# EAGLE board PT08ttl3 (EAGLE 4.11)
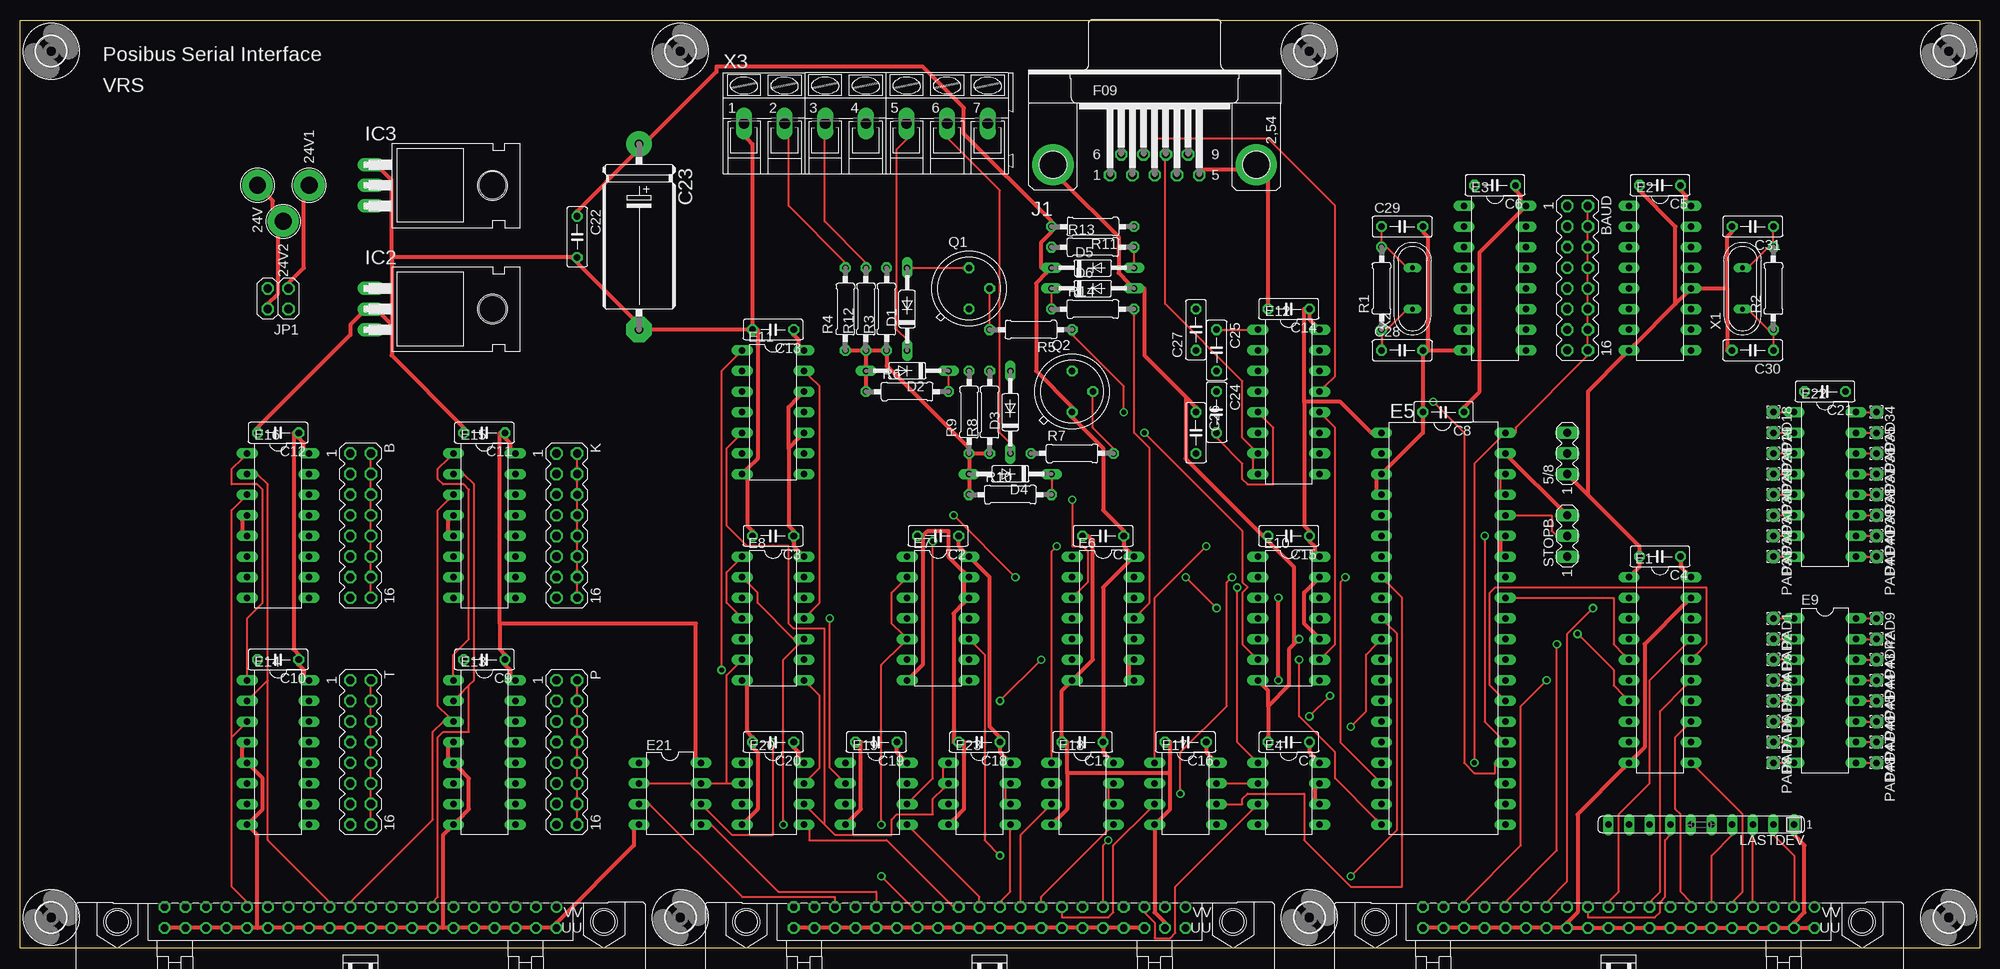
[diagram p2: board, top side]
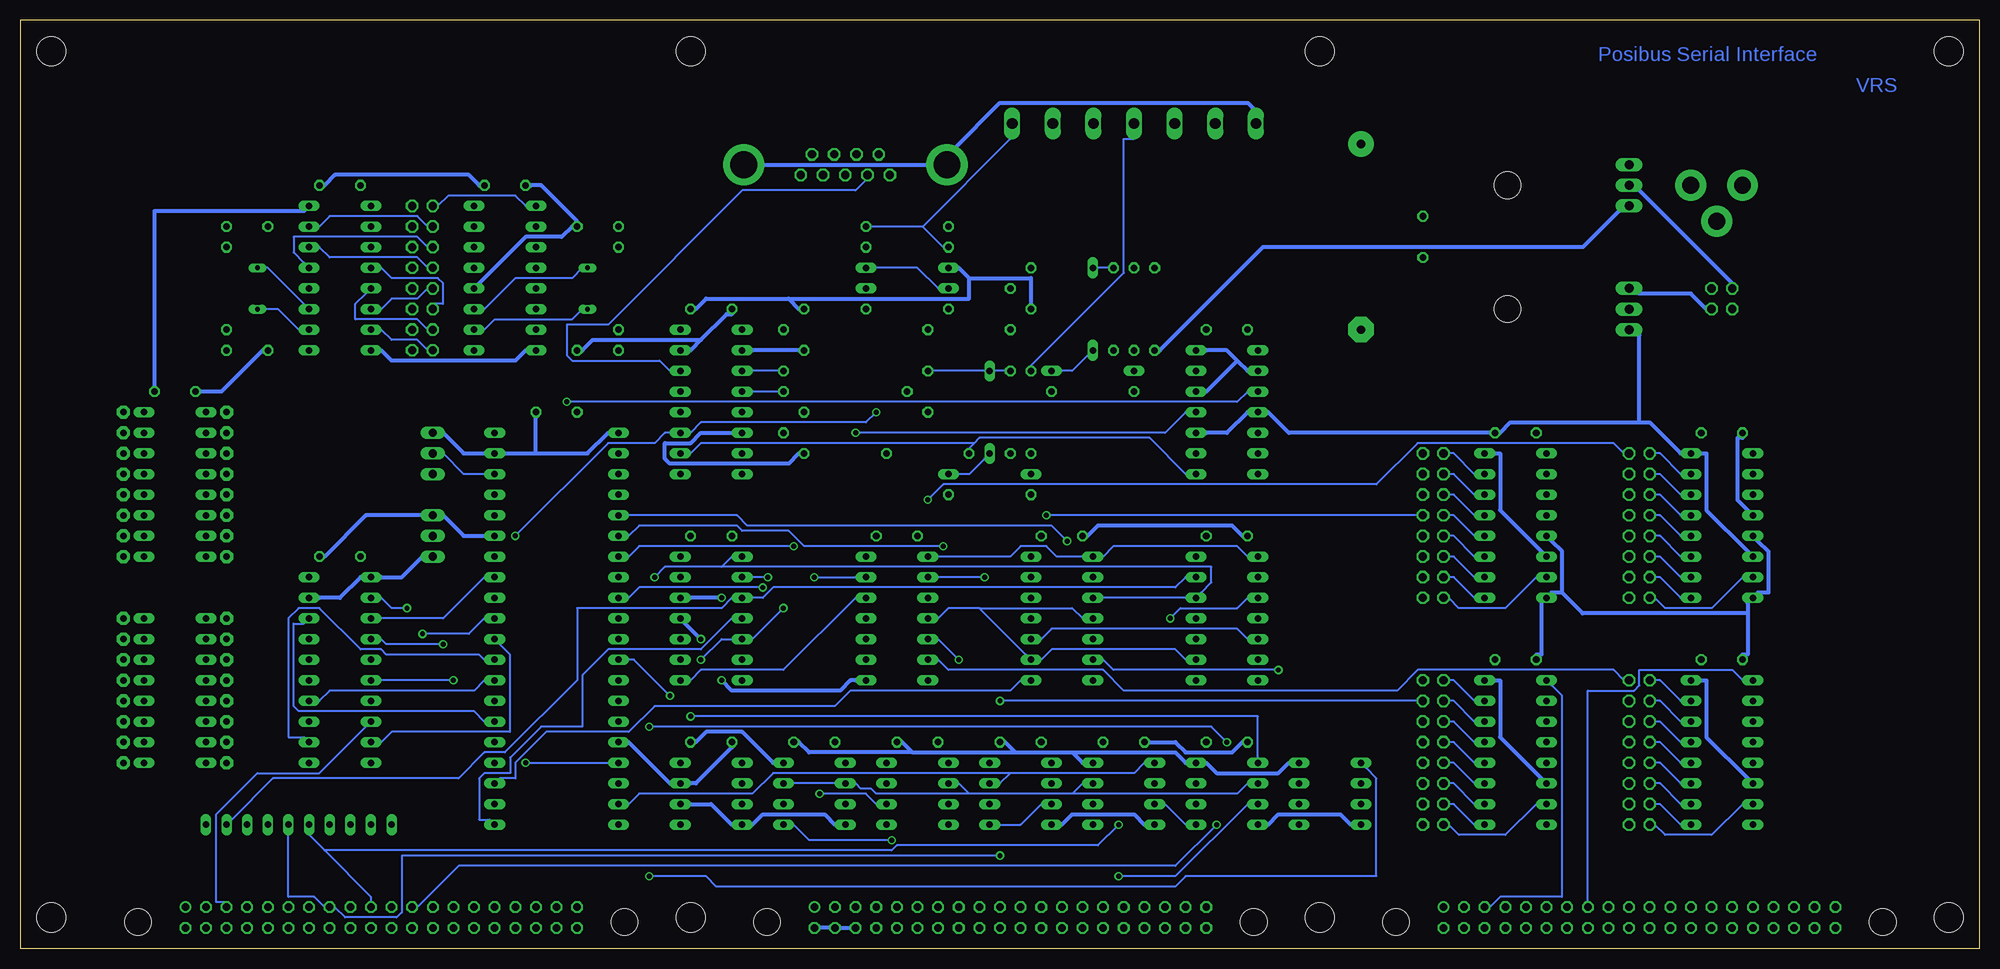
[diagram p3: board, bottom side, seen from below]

Size 241.3 x 114.3 mm. Coordinates in mm from the lower left corner, seen from the top.
Outline: 0,0 0,114.3 241.3,114.3 241.3,0 0,0
Copper layers (1*16): Top 0.035mm / dielectric 1.5mm / Bottom 0.035mm
Design rules "olimex10mil": minimum track width 10mil, minimum drill 24mil, track to track 10mil, track to pad 10mil, pad to pad 10mil, via to via 10mil, smd to smd 10mil, copper to edge 25mil, drill to drill 10mil, minimum pad ring 10mil, minimum via ring 8mil, stop-mask expansion 0mil, vias tented up to drill 0mil, thermal gap 10mil
Net classes: 1 supply: width 0.508 mm

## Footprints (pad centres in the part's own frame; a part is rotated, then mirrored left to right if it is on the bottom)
MA03-1 = drill 1.016 long: 1 -2.54,0; 2 0,0; 3 2.54,0
0820 = drill 2.083 pad 3.81 round: P$1 0,0
MA08-2 = drill 1.016 octagon: 1 -8.89,-1.27; 2 -8.89,1.27; 3 -6.35,-1.27; 4 -6.35,1.27; 5 -3.81,-1.27; 6 -3.81,1.27; 7 -1.27,-1.27; 8 -1.27,1.27; 9 1.27,-1.27; 10 1.27,1.27; 11 3.81,-1.27; 12 3.81,1.27; 13 6.35,-1.27; 14 6.35,1.27; 15 8.89,-1.27; 16 8.89,1.27
C050-025X075 = drill 0.813 octagon: 1 -2.54,0; 2 2.54,0
E22-9 = drill 1.016 pad 3.15 round: + -11.43,0 | drill 1.016 pad 3.15 octagon: - 11.43,0
DO35-10 = drill 0.813 long: A 5.08,0; C -5.08,0
DEC40PINH = drill 0.914 octagon: A 24.13,1.27; AA -3.81,1.27; B 24.13,-1.27; BB -3.81,-1.27; C 21.59,1.27; CC -6.35,1.27; D 21.59,-1.27; DD -6.35,-1.27; E 19.05,1.27; EE -8.89,1.27; F 19.05,-1.27; FF -8.89,-1.27; H 16.51,1.27; HH -11.43,1.27; J 16.51,-1.27; JJ -11.43,-1.27; K 13.97,1.27; KK -13.97,1.27; L 13.97,-1.27; LL -13.97,-1.27; M 11.43,1.27; MM -16.51,1.27; N 11.43,-1.27; NN -16.51,-1.27; P 8.89,1.27; PP -19.05,1.27; R 8.89,-1.27; RR -19.05,-1.27; S 6.35,1.27; SS -21.59,1.27; T 6.35,-1.27; TT -21.59,-1.27; U 3.81,1.27; UU -24.13,1.27; V 3.81,-1.27; W 1.27,1.27; X 1.27,-1.27; Y -1.27,1.27; Z -1.27,-1.27 | drill 0.914 round: VV -24.13,-1.27 | hole 3.302: -29.972,0.533; 29.972,0.533
DIL20 = drill 0.813 long: 1 -11.43,-3.81; 2 -8.89,-3.81; 3 -6.35,-3.81; 4 -3.81,-3.81; 5 -1.27,-3.81; 6 1.27,-3.81; 7 3.81,-3.81; 8 6.35,-3.81; 9 8.89,-3.81; 10 11.43,-3.81; 11 11.43,3.81; 12 8.89,3.81; 13 6.35,3.81; 14 3.81,3.81; 15 1.27,3.81; 16 -1.27,3.81; 17 -3.81,3.81; 18 -6.35,3.81; 19 -8.89,3.81; 20 -11.43,3.81
DIL16 = drill 0.813 long: 1 -8.89,-3.81; 2 -6.35,-3.81; 3 -3.81,-3.81; 4 -1.27,-3.81; 5 1.27,-3.81; 6 3.81,-3.81; 7 6.35,-3.81; 8 8.89,-3.81; 9 8.89,3.81; 10 6.35,3.81; 11 3.81,3.81; 12 1.27,3.81; 13 -1.27,3.81; 14 -3.81,3.81; 15 -6.35,3.81; 16 -8.89,3.81
DIL08 = drill 0.813 long: 1 -3.81,-3.81; 2 -1.27,-3.81; 3 1.27,-3.81; 4 3.81,-3.81; 5 3.81,3.81; 6 1.27,3.81; 7 -1.27,3.81; 8 -3.81,3.81
DIL40 = drill 0.813 long: 1 -24.13,-7.62; 2 -21.59,-7.62; 3 -19.05,-7.62; 4 -16.51,-7.62; 5 -13.97,-7.62; 6 -11.43,-7.62; 7 -8.89,-7.62; 8 -6.35,-7.62; 9 -3.81,-7.62; 10 -1.27,-7.62; 11 1.27,-7.62; 12 3.81,-7.62; 13 6.35,-7.62; 14 8.89,-7.62; 15 11.43,-7.62; 16 13.97,-7.62; 17 16.51,-7.62; 18 19.05,-7.62; 19 21.59,-7.62; 20 24.13,-7.62; 21 24.13,7.62; 22 21.59,7.62; 23 19.05,7.62; 24 16.51,7.62; 25 13.97,7.62; 26 11.43,7.62; 27 8.89,7.62; 28 6.35,7.62; 29 3.81,7.62; 30 1.27,7.62; 31 -1.27,7.62; 32 -3.81,7.62; 33 -6.35,7.62; 34 -8.89,7.62; 35 -11.43,7.62; 36 -13.97,7.62; 37 -16.51,7.62; 38 -19.05,7.62; 39 -21.59,7.62; 40 -24.13,7.62
DIL14 = drill 0.813 long: 1 -7.62,-3.81; 2 -5.08,-3.81; 3 -2.54,-3.81; 4 0,-3.81; 5 2.54,-3.81; 6 5.08,-3.81; 7 7.62,-3.81; 8 7.62,3.81; 9 5.08,3.81; 10 2.54,3.81; 11 0,3.81; 12 -2.54,3.81; 13 -5.08,3.81; 14 -7.62,3.81
TO220H = drill 1.118 long: 1 -2.54,-10.16; 2 0,-10.16; 3 2.54,-10.16 | hole 3.302: 0,4.826
F09HP = drill 1.016 octagon: 1 -5.486,-1.27; 2 -2.743,-1.27; 3 0,-1.27; 4 2.743,-1.27; 5 5.486,-1.27; 6 -4.115,1.27; 7 -1.372,1.27; 8 1.372,1.27; 9 4.115,1.27 | drill 3.302 pad 5.08 round: G1 -12.522,0; G2 12.522,0
2X02 = drill 1.016 octagon: 1 -1.27,-1.27; 2 -1.27,1.27; 3 1.27,-1.27; 4 1.27,1.27
SIL10 = drill 0.813 long: 1 -11.43,0; 2 -8.89,0; 3 -6.35,0; 4 -3.81,0; 5 -1.27,0; 6 1.27,0; 7 3.81,0; 8 6.35,0; 9 8.89,0; 10 11.43,0
1,6/0,8 = drill 0.813 pad 1.6 octagon: 1 0,0
TO39 = drill 0.813 octagon: 1 0,-2.54; 2 2.54,0; 3 0,2.54
0207/10 = drill 0.813 octagon: 1 -5.08,0; 2 5.08,0
3,6 = hole 3.6: 0,0
QS = drill 0.61 long: 1 -2.54,0; 2 2.54,0
AK300/7 = drill 1.321 long: 1 -15.011,0; 2 -10.008,0; 3 -5.004,0; 4 0,0; 5 5.004,0; 6 10.008,0; 7 15.011,0

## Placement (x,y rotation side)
5/8  [MA03-1]  190.5,60.96 90 top
24V  PAD-0820  [0820]  29.21,93.98 270 top
24V1  PAD-0820  [0820]  35.56,93.98 90 top
24V2  PAD-0820  [0820]  32.38,89.53 270 top
B  [MA08-2]  41.91,52.07 270 top
BAUD  [MA08-2]  191.77,82.55 270 top
C1  0.1  [C050-025X075]  133.35,50.8 180 top
C2  0.1  [C050-025X075]  113.03,50.8 180 top
C3  0.1  [C050-025X075]  92.71,50.8 180 top
C4  0.1  [C050-025X075]  201.93,48.26 180 top
C5  0.1  [C050-025X075]  201.93,93.98 180 top
C6  0.1  [C050-025X075]  181.61,93.98 180 top
C7  0.1  [C050-025X075]  156.21,25.4 180 top
C8  0.1  [C050-025X075]  175.26,66.04 180 top
C9  0.1  [C050-025X075]  57.15,35.56 180 top
C10  0.1  [C050-025X075]  31.75,35.56 180 top
C11  0.1  [C050-025X075]  57.15,63.5 180 top
C12  0.1  [C050-025X075]  31.75,63.5 180 top
C13  0.1  [C050-025X075]  92.71,76.2 180 top
C14  0.1  [C050-025X075]  156.21,78.74 180 top
C15  0.1  [C050-025X075]  156.21,50.8 180 top
C16  0.1  [C050-025X075]  143.51,25.4 180 top
C17  0.1  [C050-025X075]  130.81,25.4 180 top
C18  0.1  [C050-025X075]  118.11,25.4 180 top
C19  0.1  [C050-025X075]  105.41,25.4 180 top
C20  0.1  [C050-025X075]  92.71,25.4 180 top
C21  0.1  [C050-025X075]  222.25,68.58 180 top
C22  0.1  [C050-025X075]  68.58,87.63 270 top
C23  100uf  [E22-9]  76.2,87.63 270 top
C24  0.1  [C050-025X075]  147.32,66.04 270 top
C25  0.1  [C050-025X075]  147.32,73.66 270 top
C26  0.1  [C050-025X075]  144.78,63.5 270 top
C27  0.1  [C050-025X075]  144.78,76.2 90 top
C28  22pf  [C050-025X075]  170.18,73.66 0 top
C29  22pf  [C050-025X075]  170.18,88.9 0 top
C30  22pf  [C050-025X075]  213.36,73.66 180 top
C31  22pf  [C050-025X075]  213.36,88.9 180 top
D1  D664  [DO35-10]  109.22,78.74 90 top
D2  D664  [DO35-10]  109.22,71.12 180 top
D3  D664  [DO35-10]  121.92,66.04 90 top
D4  D664  [DO35-10]  121.92,58.42 180 top
D5  D664  [DO35-10]  132.08,83.82 0 top
D6  D664  [DO35-10]  132.08,81.28 0 top
D34L  [DEC40PINH]  119.38,3.81 180 top
D35L  [DEC40PINH]  41.91,3.81 180 top
D36L  [DEC40PINH]  196.85,3.81 180 top
E1  74HCT240N  [DIL20]  201.93,34.29 270 top
E2  74HCT4060N  [DIL16]  201.93,82.55 270 top
E3  74HCT4060N  [DIL16]  181.61,82.55 270 top
E4  DS75452N  [DIL08]  156.21,19.05 270 top
E5  HD6402  [DIL40]  175.26,39.37 270 top
E6  74LS02N  [DIL14]  133.35,40.64 270 top
E7  74HCT00N  [DIL14]  113.03,40.64 270 top
E8  74HCT08N  [DIL14]  92.71,40.64 270 top
E9  SPARE  [DIL16]  222.25,31.75 270 top
E10  74HCT04N  [DIL14]  156.21,40.64 270 top
E11  74HCT74N  [DIL14]  92.71,66.04 270 top
E12  MAX232  [DIL16]  156.21,67.31 270 top
E13  74LS138N  [DIL16]  57.15,24.13 270 top
E14  74LS138N  [DIL16]  31.75,24.13 270 top
E15  74LS138N  [DIL16]  57.15,52.07 270 top
E16  74LS138N  [DIL16]  31.75,52.07 270 top
E17  DS75452N  [DIL08]  143.51,19.05 270 top
E18  DS75452N  [DIL08]  130.81,19.05 270 top
E19  DS75452N  [DIL08]  105.41,19.05 270 top
E20  DS75452N  [DIL08]  92.71,19.05 270 top
E21  DS75452N  [DIL08]  80.01,19.05 270 top
E22  SPARE  [DIL16]  222.25,57.15 270 top
E23  DS75452N  [DIL08]  118.11,19.05 270 top
IC2  7805T  [TO220H]  53.34,78.74 270 top
IC3  7915T  [TO220H]  53.34,93.98 270 top
J1  [F09HP]  139.7,96.52 0 top
JP1  [2X02]  31.75,80.01 180 top
K  [MA08-2]  67.31,52.07 270 top
LASTDEV  100  [SIL10]  207.01,15.24 180 top
P  [MA08-2]  67.31,24.13 270 top
PAD1  [1,6/0,8]  215.9,40.64 270 top
PAD2  [1,6/0,8]  215.9,38.1 270 top
PAD3  [1,6/0,8]  215.9,35.56 270 top
PAD4  [1,6/0,8]  215.9,33.02 270 top
PAD5  [1,6/0,8]  215.9,30.48 270 top
PAD6  [1,6/0,8]  215.9,27.94 270 top
PAD7  [1,6/0,8]  215.9,25.4 270 top
PAD8  [1,6/0,8]  215.9,22.86 270 top
PAD9  [1,6/0,8]  228.6,40.64 270 top
PAD18  [1,6/0,8]  215.9,66.04 270 top
PAD19  [1,6/0,8]  215.9,63.5 270 top
PAD28  [1,6/0,8]  215.9,60.96 270 top
PAD29  [1,6/0,8]  215.9,58.42 270 top
PAD30  [1,6/0,8]  215.9,55.88 270 top
PAD31  [1,6/0,8]  215.9,53.34 270 top
PAD32  [1,6/0,8]  215.9,50.8 270 top
PAD33  [1,6/0,8]  215.9,48.26 270 top
PAD34  [1,6/0,8]  228.6,66.04 270 top
PAD35  [1,6/0,8]  228.6,63.5 270 top
PAD36  [1,6/0,8]  228.6,60.96 270 top
PAD37  [1,6/0,8]  228.6,58.42 270 top
PAD38  [1,6/0,8]  228.6,55.88 270 top
PAD39  [1,6/0,8]  228.6,53.34 270 top
PAD40  [1,6/0,8]  228.6,50.8 270 top
PAD41  [1,6/0,8]  228.6,48.26 270 top
PAD42  [1,6/0,8]  228.6,38.1 270 top
PAD43  [1,6/0,8]  228.6,35.56 270 top
PAD44  [1,6/0,8]  228.6,33.02 270 top
PAD45  [1,6/0,8]  228.6,30.48 270 top
PAD46  [1,6/0,8]  228.6,27.94 270 top
PAD47  [1,6/0,8]  228.6,25.4 270 top
PAD48  [1,6/0,8]  228.6,22.86 270 top
Q1  2N2904  [TO39]  116.84,81.28 0 top
Q2  2N2904  [TO39]  129.54,68.58 0 top
R1  10M  [0207/10]  167.64,81.28 90 top
R2  10M  [0207/10]  215.9,81.28 90 top
R3  1.5K 1/2W  [0207/10]  106.68,78.74 90 top
R4  750 1W  [0207/10]  101.6,78.74 90 top
R5  470  [0207/10]  124.46,76.2 180 top
R6  15K 1/2W  [0207/10]  109.22,68.58 0 top
R7  470  [0207/10]  129.54,60.96 0 top
R8  1.5K 1/2W  [0207/10]  119.38,66.04 90 top
R9  750 1W  [0207/10]  116.84,66.04 90 top
R10  15K 1/2W  [0207/10]  121.92,55.88 0 top
R11  750 1/2W  [0207/10]  132.08,88.9 180 top
R12  560 1/2W  [0207/10]  104.14,78.74 90 top
R13  82  [0207/10]  132.08,86.36 0 top
R14  3.3K  [0207/10]  132.08,78.74 0 top
STOPB  [MA03-1]  190.5,50.8 90 top
T  [MA08-2]  41.91,24.13 270 top
U$1  [3,6]  237.49,3.81 0 top
U$2  [3,6]  237.49,110.49 0 top
U$3  [3,6]  3.81,110.49 0 top
U$4  [3,6]  3.81,3.81 0 top
U$5  [3,6]  158.75,110.49 0 top
U$6  [3,6]  81.28,3.81 0 top
U$7  [3,6]  158.75,3.81 0 top
U$8  [3,6]  81.28,110.49 0 top
X1  2.4576Mhz  [QS]  212.09,81.28 90 top
X2  3.579545Mhz  [QS]  171.45,81.28 90 top
X3  [AK300/7]  104.14,101.6 0 top

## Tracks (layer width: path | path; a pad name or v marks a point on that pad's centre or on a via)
24V1
  Top 0.508: JP1.1 33.02,81.92 34.92,83.82 34.92,92.71 24V1.P$1
24V2
  Top 0.508: JP1.4 30.48,79.38 31.75,80.64 31.75,88.27 24V2.P$1 31.11,90.81 31.11,92.08 30.48,92.71 24V.P$1
+24V
  Bottom 0.508: JP1.2 33.66,78.74 35.56,80.64 41.91,80.64 IC2.1
-15V
  Top 0.508: R10.1 116.84,56.52 116.84,57.78 D4.A 116.84,59.05 116.84,60.33 R9.1 | R8.1 118.75,60.96 117.47,60.96 R9.1 | R6.1 104.14,69.22 104.14,70.48 D2.A 104.14,71.75 104.14,73.03 R12.1 | R4.1 102.23,73.66 103.5,73.66 R12.1 | R12.1 104.78,73.66 106.05,73.66 R3.1 106.68,73.03 106.68,71.75 116.84,61.59 R9.1
  Bottom 0.508: IC3.3 44.45,90.81 48.9,86.36 88.27,86.36 100.97,73.66 R4.1
-24V
  Bottom 0.508: JP1.3 30.48,81.92 41.91,93.34 IC3.2
ACB04\
  Top 0.254: E19.5 109.86,14.61 118.11,6.35 118.11,5.71 D34L.X
ACB05\
  Top 0.254: E18.3 126.36,17.14 123.19,13.97 123.19,5.71 D34L.BB
ACB06\
  Top 0.254: E17.3 139.06,17.14 134.62,12.7 134.62,4.45 133.99,3.81 128.27,3.81 128.27,4.45 D34L.FF
ACB07\  (via drill 0.61)
  Top 0.254: v133.99,13.34 133.35,12.7 133.35,5.71 D34L.LL
  Bottom 0.254: v133.99,13.34 144.15,13.34 146.05,15.24 E17.5
ACB08\
  Top 0.254: E4.3 151.76,17.14 142.24,7.62 142.24,1.91 141.6,1.27 139.7,1.27 139.7,3.17 138.43,4.45 D34L.RR
ACB09\
  Top 0.254: E21.3 77.47,17.78 88.9,6.35 100.33,6.35 100.33,5.71 D34L.F
ACB10\
  Top 0.254: E21.5 85.09,15.24 93.34,6.99 105.41,6.99 105.41,5.71 D34L.L
ACB11\  (via drill 0.61)
  Top 0.254: v106.05,8.89 109.86,5.08 D34L.R
  Bottom 0.254: v106.05,8.89 99.06,8.89 90.17,17.78 E20.3
ACCLEAR\
  Top 0.254: E18.5 133.99,14.61 125.73,6.35 125.73,5.71 D34L.DD
B110
  Bottom 0.254: E3.1 179.07,91.44 180.34,92.71 188.59,92.71 189.87,91.44 BAUD.1
B150
  Bottom 0.254: E2.15 204.47,88.9 203.2,90.17 192.41,90.17 191.13,88.9 BAUD.3
B300
  Bottom 0.254: E2.13 206.38,84.45 207.65,85.72 207.65,87.63 192.41,87.63 191.13,86.36 BAUD.5
B600
  Bottom 0.254: E2.14 204.47,86.36 203.2,85.09 192.41,85.09 191.13,83.82 BAUD.7
B1200
  Bottom 0.254: E2.6 196.85,78.74 195.58,80.01 192.41,80.01 191.13,81.28 BAUD.9
B2400
  Bottom 0.254: E2.4 196.85,83.82 195.58,82.55 189.87,82.55 189.23,81.92 189.23,79.38 190.5,79.38 BAUD.11
B4800
  Bottom 0.254: E2.5 198.75,80.64 200.03,79.38 200.03,77.47 192.41,77.47 191.13,76.2 BAUD.13
B9600
  Bottom 0.254: E2.7 196.85,76.2 195.58,74.93 192.41,74.93 191.13,73.66 BAUD.15
B\  (via drill 0.61)
  Top 0.254: B.16 43.18,43.81 43.18,45.09 B.14 43.18,46.35 43.18,47.62 B.12 43.18,48.9 43.18,50.16 B.10 43.18,51.44 43.18,52.7 B.8 43.18,53.98 43.18,55.24 B.6 43.18,56.52 43.18,57.78 B.4 43.18,59.05 43.18,60.33 B.2 | v129.54,55.24 129.54,49.53 130.81,49.53 131.44,48.9 131.44,45.09 130.18,43.81 E6.3
  Bottom 0.254: v129.54,55.24 127.64,57.15 74.3,57.15 69.22,62.23 45.09,62.23 43.81,60.96 B.2
BAC04
  Top 0.254: E1.17 205.1,37.47 200.66,33.02 200.66,20.32 196.85,16.51 196.85,6.99 195.58,5.71 D36L.X
BAC05
  Top 0.254: E1.15 205.1,32.38 201.93,29.21 201.93,6.99 200.66,5.71 D36L.BB
BAC06
  Top 0.254: E1.13 205.1,27.3 203.84,26.04 203.84,17.14 204.47,16.51 204.47,6.99 205.74,5.71 D36L.FF
BAC07
  Top 0.254: E1.11 206.38,22.23 212.09,16.51 212.09,6.99 210.82,5.71 D36L.LL
BAC08
  Bottom 0.254: E1.8 198.75,27.3 204.47,21.59 212.09,21.59 217.17,16.51 217.17,5.71 215.9,5.71 D36L.RR
BAC09  (via drill 0.61)
  Top 0.254: v187.96,33.02 184.78,29.84 184.78,12.7 177.8,5.71 D36L.F
  Bottom 0.254: v187.96,33.02 196.85,33.02 E1.6
BAC10  (via drill 0.61)
  Top 0.254: v189.23,37.47 189.23,12.06 182.88,5.71 D36L.L
  Bottom 0.254: v189.23,37.47 196.22,37.47 196.85,38.1 E1.4
BAC11  (via drill 0.61)
  Top 0.254: v193.68,41.91 190.5,38.73 190.5,8.26 187.96,5.71 D36L.R
  Bottom 0.254: v193.68,41.91 195.58,41.91 196.85,43.18 E1.2
BCLK  (via drill 0.61)
  Top 0.254: BAUD.2 193.04,90.81 193.04,89.53 BAUD.4 193.04,88.27 193.04,87 BAUD.6 193.04,85.72 193.04,84.45 BAUD.8 193.04,83.19 193.04,81.92 BAUD.10 193.04,80.64 193.04,79.38 BAUD.12 193.04,78.11 193.04,76.83 BAUD.14 193.04,75.56 193.04,74.3 BAUD.16 193.04,73.03 184.15,64.14 184.15,63.5 E5.40 182.25,62.87 179.07,59.69 v179.07,22.86
  Bottom 0.254: v179.07,22.86 168.91,22.86 E5.17
BINIT\
  Top 0.254: LASTDEV.2 215.9,13.97 218.44,11.43 218.44,5.71 D36L.TT
  Bottom 0.254: E8.13 97.79,45.72 99.06,44.45 148.59,44.45 149.86,43.18 151.13,43.18 E10.3 153.67,43.18 154.94,41.91 172.72,41.91 172.72,33.02 181.61,24.13 184.15,24.13 187.32,20.95 210.19,20.95 215.26,15.88 LASTDEV.2
BIOP1  (via drill 0.61)
  Top 0.254: E8.2 89.53,45.09 90.81,43.81 90.81,42.55 95.25,38.1 E8.10 95.89,37.47 93.98,35.56 v93.98,15.24 | LASTDEV.7 203.2,13.97 202.56,13.34 202.56,6.35 201.93,5.71 201.93,4.45 201.29,3.81 193.04,3.81 193.04,4.45 D36L.V
  Bottom 0.254: v93.98,15.24 99.06,10.16 187.32,10.16 192.41,5.08 D36L.V
BIOP2  (via drill 0.61)
  Top 0.254: E7.2 108.58,45.09 107.31,43.81 107.31,40.01 108.58,38.73 E7.5 108.58,37.47 106.05,34.92 v106.05,15.24
  Bottom 0.254: 203.84,12.06 198.12,6.35 198.12,5.71 D36L.Z | 203.84,12.06 205.74,13.97 LASTDEV.6 | v106.05,15.24 108.58,12.7 133.35,12.7 133.99,12.06 203.84,12.06
BIOP4  (via drill 0.61)
  Top 0.254: v120.65,11.43 118.75,13.34 118.75,36.2 117.47,37.47 E7.10
  Bottom 0.254: LASTDEV.5 208.28,13.97 208.28,6.35 205.1,6.35 203.84,5.08 D36L.DD 202.56,5.08 201.29,3.81 194.94,3.81 194.31,4.45 194.31,11.43 v120.65,11.43 | E8.5 90.17,38.1 91.44,39.37 114.3,39.37 115.57,38.1 E7.10
BMB03
  Top 0.254: E15.3 52.7,55.24 51.44,53.98 51.44,29.84 52.7,28.57 E13.3 52.07,27.94 50.8,26.67 50.8,15.88 40.64,5.71 D35L.X
BMB04
  Top 0.254: 55.24,32.38 55.88,33.02 55.88,57.15 54.61,58.42 E15.2 | 55.24,32.38 53.98,31.11 E13.2 | 55.24,32.38 55.24,26.67 52.07,26.67 51.44,26.04 51.44,6.35 50.8,5.71 D35L.FF
BMB05
  Top 0.254: E15.1 52.7,60.33 51.44,59.05 51.44,57.78 52.07,57.15 54.61,57.15 55.24,56.52 55.24,38.1 53.34,36.2 53.34,33.66 E13.1
  Bottom 0.254: E13.1 52.7,32.38 51.44,31.11 51.44,6.35 59.05,6.35 60.33,5.08 D35L.RR
BMB06
  Top 0.254: 26.04,26.04 27.3,27.3 E14.3 | 26.04,26.04 26.04,7.62 27.94,5.71 D35L.L | 26.04,26.04 26.04,53.98 27.3,55.24 E16.3
BMB07
  Top 0.254: 30.48,33.02 28.57,31.11 E14.2 | 30.48,33.02 30.48,57.15 29.21,58.42 E16.2 | 30.48,33.02 30.48,13.34 38.1,5.71 D35L.V
BMB08
  Top 0.254: E14.1 27.94,33.66 27.94,40.64 29.84,42.55 29.84,56.52 29.21,57.15 26.04,57.15 26.04,59.05 27.3,60.33 E16.1
  Bottom 0.254: D35L.DD 48.26,5.71 48.26,31.75 42.55,31.75 41.91,32.38 41.91,34.29 30.48,34.29 29.21,33.02 E14.1
BTS1
  Top 0.254: LASTDEV.3 213.36,13.97 213.36,5.71 D36L.NN
BTS3
  Top 0.254: LASTDEV.4 210.82,13.97 208.28,11.43 208.28,5.71 D36L.JJ
CS8
  Top 0.254: E5.37 182.25,56.52 182.25,57.78 E5.38
  Bottom 0.254: 5/8.2 189.23,60.96 186.69,58.42 184.15,58.42 E5.38
GND  (via drill 0.61)
  Top 0.508: C3.2 90.17,51.44 89.53,52.07 89.53,57.78 E11.7 89.53,59.05 90.81,60.33 90.81,76.2 C13.2 | C13.2 89.53,76.2 77.47,76.2 C23.- 75.56,77.47 68.58,84.45 C22.2 67.94,85.09 45.72,85.09 | X3.1 89.53,99.69 90.17,99.06 90.17,76.83 C13.2 | E15.5 52.7,51.44 52.7,52.7 E15.4 | E16.5 27.3,51.44 27.3,52.7 E16.4 | E13.4 52.7,24.77 52.7,23.5 E13.5 53.98,22.23 55.24,20.95 55.24,17.14 53.98,15.88 E13.8 52.7,14.61 52.07,13.97 52.07,2.54 | E14.4 27.3,24.77 27.3,23.5 E14.5 28.57,22.23 29.84,20.95 29.84,17.14 28.57,15.88 E14.8 28.57,14.61 29.21,13.97 29.21,2.54 | D35L.A 18.41,2.54 19.68,2.54 D35L.C 20.95,2.54 22.23,2.54 D35L.E 23.5,2.54 24.77,2.54 D35L.H 26.04,2.54 27.3,2.54 D35L.K 28.57,2.54 29.21,2.54 | 29.21,2.54 29.84,2.54 D35L.M 31.11,2.54 32.38,2.54 D35L.P 33.66,2.54 34.92,2.54 D35L.S 36.2,2.54 37.47,2.54 D35L.U 38.73,2.54 40.01,2.54 D35L.W 41.27,2.54 42.55,2.54 D35L.Y 43.81,2.54 45.09,2.54 D35L.AA 46.35,2.54 47.62,2.54 D35L.CC 48.9,2.54 50.16,2.54 D35L.EE 51.44,2.54 52.07,2.54 | 52.07,2.54 52.7,2.54 D35L.HH 53.98,2.54 55.24,2.54 D35L.KK 56.52,2.54 57.78,2.54 D35L.MM 59.05,2.54 60.33,2.54 D35L.PP 61.59,2.54 62.87,2.54 D35L.SS 64.14,2.54 65.41,2.54 D35L.UU 66.04,3.17 75.56,12.7 75.56,14.61 E21.4 | E8.7 89.53,32.38 89.53,26.67 90.17,26.04 C20.2 90.17,24.77 90.81,24.13 90.81,17.14 89.53,15.88 E20.4 | 111.12,50.8 111.12,34.92 109.86,33.66 E7.7 | 111.12,50.8 C2.2 111.12,50.8 | E19.4 102.23,15.88 103.5,17.14 103.5,25.4 C19.2 | E23.4 114.94,15.88 116.2,17.14 116.2,25.4 C18.2 114.94,25.4 114.94,41.27 116.2,42.55 E7.12 116.2,43.81 116.2,45.09 E7.13 116.2,46.35 114.3,48.26 114.3,51.44 111.76,51.44 111.12,50.8
  Top 0.508: LASTDEV.1 218.44,13.97 219.71,12.7 219.71,4.45 218.44,3.17 D36L.SS | D36L.UU 220.34,2.54 219.07,2.54 D36L.SS | D36L.A 173.35,2.54 174.62,2.54 D36L.C 175.9,2.54 177.16,2.54 D36L.E 178.44,2.54 179.71,2.54 D36L.H 180.97,2.54 182.25,2.54 D36L.K 183.51,2.54 184.78,2.54 D36L.M 186.06,2.54 187.32,2.54 D36L.P 188.59,2.54 189.87,2.54 D36L.S | D36L.S 191.13,2.54 192.41,2.54 D36L.U 193.68,2.54 194.94,2.54 D36L.W 196.22,2.54 197.49,2.54 D36L.Y 198.75,2.54 200.03,2.54 D36L.AA 201.29,2.54 202.56,2.54 D36L.CC 203.84,2.54 205.1,2.54 D36L.EE 206.38,2.54 207.65,2.54 D36L.HH 208.91,2.54 210.19,2.54 D36L.KK 211.46,2.54 212.72,2.54 D36L.MM 214,2.54 215.26,2.54 D36L.PP 216.53,2.54 217.81,2.54 D36L.SS | 203.84,79.38 205.1,80.64 E2.12 207.01,81.28 210.19,81.28 | 203.84,79.38 198.75,74.3 E2.8 197.49,73.03 193.04,68.58 193.04,55.88 | 203.84,79.38 203.84,88.9 199.39,93.34 C5.2 | 210.19,81.28 210.19,73.66 C30.2 | 210.19,81.28 210.19,87.63 210.82,88.27 C31.2 | E1.1 198.75,46.35 199.39,46.99 199.39,47.62 C4.2 199.39,48.9 199.39,49.53 193.04,55.88 | 193.04,55.88 191.13,57.78 5/8.1 | E1.19 205.1,42.55 200.03,37.47 200.03,24.77 198.75,23.5 E1.10 197.49,22.23 191.77,16.51 191.77,4.45 190.5,3.17 D36L.S | E5.4 167,56.52 167,57.78 E5.3 168.28,59.05 172.72,63.5 172.72,65.41 C8.2 172.72,66.67 172.72,73.03 C28.2 | 173.35,73.66 176.53,73.66 E3.8 | 173.35,73.66 C28.2 | 173.35,73.66 173.35,87.63 172.72,88.27 C29.2 | 173.35,73.66 C28.2 | J1.5 145.41,95.89 149.86,95.89 J1.G2 153.67,94.61 153.67,79.38 C14.2 | D34L.A 95.89,2.54 97.16,2.54 D34L.C 98.42,2.54 99.69,2.54 D34L.E 100.97,2.54 102.23,2.54 D34L.H 103.5,2.54 104.78,2.54 D34L.K 106.05,2.54 107.31,2.54 D34L.M 108.58,2.54 109.86,2.54 D34L.P 111.12,2.54 112.39,2.54 D34L.S 113.67,2.54 114.94,2.54 D34L.U 116.2,2.54 117.47,2.54 D34L.W 118.75,2.54 120.02,2.54 D34L.Y 121.28,2.54 122.56,2.54 D34L.AA 123.83,2.54 125.09,2.54 D34L.CC 126.36,2.54 127.64,2.54 D34L.EE 128.91,2.54 130.18,2.54 D34L.HH 131.44,2.54 132.72,2.54 D34L.KK 133.99,2.54 135.25,2.54 D34L.MM 136.53,2.54 137.79,2.54 D34L.PP
  Top 0.508: 143.51,67.94 138.43,73.03 138.43,81.28 D6.A 136.53,81.92 135.25,83.19 135.25,87.63 128.27,94.61 J1.G1 | 143.51,67.94 144.78,66.67 C26.1 | 143.51,67.94 143.51,60.33 153.03,50.8 C15.2 153.67,50.16 156.84,46.99 156.84,37.47 | 153.67,29.84 153.67,26.04 C7.2 | 153.67,29.84 153.67,31.75 153.03,32.38 E10.7 | 156.84,37.47 156.21,36.83 156.21,32.38 153.67,29.84 | 156.84,37.47 v157.48,38.1 | E4.7 159.38,19.68 159.38,18.41 E4.6 | 141.6,21.59 141.6,25.4 C16.2 | 141.6,21.59 141.6,17.14 140.34,15.88 E17.4 139.7,14.61 139.7,4.45 140.97,3.17 D34L.SS | 128.91,21.59 128.91,25.4 C17.2 128.27,26.04 128.27,31.75 128.91,32.38 E6.7 130.18,33.66 132.08,35.56 132.08,50.16 131.44,50.8 C1.2 | 128.91,21.59 128.91,17.14 127.64,15.88 E18.4 | 141.6,21.59 128.91,21.59 | 45.72,76.83 45.72,73.03 54.61,64.14 C11.2 | 45.72,76.83 44.45,78.11 IC2.2 41.91,78.11 40.64,76.83 40.64,75.56 29.21,64.14 C12.2 | 45.72,85.09 45.72,76.83 | 45.72,85.09 45.72,94.61 44.45,95.89 IC3.1
  Bottom 0.508: C9.2 54.61,36.2 53.98,36.2 53.98,42.55 E15.8 52.7,43.81 51.44,43.81 | 51.44,43.81 51.44,48.9 52.7,50.16 E15.5 | 28.57,41.27 28.57,36.2 29.21,36.2 C10.2 | 28.57,41.27 28.57,42.55 E16.8 27.3,43.81 26.04,43.81 26.04,48.9 27.3,50.16 E16.5 | E16.4 28.57,53.98 29.84,55.24 29.84,62.87 29.21,62.87 C12.2 | 51.44,43.81 48.9,41.27 28.57,41.27 | E21.4 77.47,15.24 78.74,16.51 86.36,16.51 87.63,15.24 E20.4 | E19.4 102.87,15.24 104.14,16.51 111.76,16.51 113.03,15.24 E23.4 | C20.2 90.81,25.4 92.08,24.13 97.79,24.13 99.06,25.4 102.23,25.4 C19.2 | C3.2 90.81,50.8 92.08,52.07 108.58,52.07 109.86,50.8 C2.2 | C30.2 211.46,73.66 216.53,68.58 219.07,68.58 C21.2 | STOPB.1 191.77,48.26 194.31,45.72 196.85,45.72 E1.1 199.39,45.72 201.93,43.18 204.47,43.18 E1.19 | C6.2 178.44,93.98 177.16,93.98 172.72,89.53 C29.2 173.35,88.9 174.62,87.63 179.07,87.63 184.78,81.92 E3.12 | 157.48,74.93 154.31,78.11 153.67,78.11 C14.2 | 157.48,74.93 158.75,73.66 E12.15 | J1.G2 149.86,96.52 129.54,96.52 J1.G1 126.36,98.42 120.65,104.14 90.17,104.14 89.53,103.5 X3.1 | 157.48,74.93 170.81,74.93 172.09,73.66 C28.2 | D34L.PP 139.06,2.54 140.34,2.54 D34L.SS 141.6,2.54 142.88,2.54 D34L.UU | v157.48,38.1 159.38,40.01 E10.11 | E4.6 158.75,17.78 156.21,17.78 153.67,15.24 E4.4 151.13,15.24 149.86,16.51 142.24,16.51 140.97,15.24 E17.4 | E5.16 166.37,25.4 161.29,20.32 E4.7 158.75,20.32 158.12,20.32 153.67,24.77 C7.2 | E2.8 196.85,73.66 195.58,72.39 180.34,72.39 179.07,73.66 E3.8
INT_RQ\
  Top 0.254: D34L.Z 120.65,5.71 121.92,6.99 121.92,14.61 E23.5
  Bottom 0.254: E23.3 115.57,17.78 118.11,15.24 120.65,15.24 E23.5
IOS\
  Top 0.254: D34L.V 114.94,5.08 106.68,13.34 97.16,13.34 97.16,14.61 E20.5
  Bottom 0.254: E20.5 97.79,15.24 100.33,17.78 E19.3
K\  (via drill 0.61)
  Top 0.254: K.16 68.58,43.81 68.58,45.09 K.14 68.58,46.35 68.58,47.62 K.12 68.58,48.9 68.58,50.16 K.10 68.58,51.44 68.58,52.7 K.8 68.58,53.98 68.58,55.24 K.6 68.58,56.52 68.58,57.78 K.4 68.58,59.05 68.58,60.33 K.2 | v114.94,53.34 v122.56,45.72
  Bottom 0.254: v122.56,45.72 128.27,45.72 E6.2 | v114.94,53.34 69.22,53.34 K.8
KB
  Top 0.254: E8.4 88.27,41.27 87,42.55 87,46.35 88.27,47.62 E8.1
  Bottom 0.254: E8.1 90.17,48.26 91.44,49.53 106.68,49.53 107.95,48.26 E7.1 110.49,48.26 113.67,48.26 114.94,49.53 118.11,49.53 119.38,48.26 128.27,48.26 E6.1
KBF
  Top 0.254: E23.6 121.28,18.41 121.28,19.68 E23.7
  Bottom 0.254: 119.38,21.59 104.14,21.59 102.87,22.86 E19.1 | 119.38,21.59 120.65,20.32 E23.7 | 119.38,21.59 148.59,21.59 151.13,19.05 165.1,19.05 166.37,17.78 E5.19
KCC  (via drill 0.61)
  Top 0.254: E18.6 133.99,18.41 133.99,19.68 E18.7 | v149.22,45.72 148.59,45.09 148.59,29.84 142.88,24.13 v142.88,19.05
  Bottom 0.254: v149.22,45.72 151.13,45.72 E10.2 | v142.88,19.05 137.16,19.05 135.89,17.78 E18.6
KCC\  (via drill 0.61)
  Top 0.254: v163.19,45.72 162.56,45.09 162.56,25.4 167,20.95 E5.18
  Bottom 0.254: E7.3 107.95,43.18 97.79,43.18 E8.12 95.89,43.81 94.61,45.09 94.61,46.99 154.94,46.99 | v163.19,45.72 161.93,46.99 154.94,46.99 | 154.94,46.99 153.67,48.26 E10.1
KRS
  Top 0.254: E21.2 77.47,20.32 82.55,20.32 E21.7 85.09,20.32 87,20.32 | 87,20.32 87.63,20.32 E20.2 | 87,20.32 87,33.66 88.27,34.92 E8.6 | E4.2 151.13,20.32 148.59,20.32 E17.7
  Bottom 0.254: E17.7 146.05,20.32 140.97,20.32 E17.2 138.43,20.32 137.79,19.68 136.53,19.68 135.89,19.05 124.46,19.05 | 111.76,19.05 110.49,20.32 E19.7 | 111.76,19.05 124.46,19.05 | 124.46,19.05 125.73,20.32 E18.2 | 111.76,19.05 91.44,19.05 90.17,20.32 E20.2
KSF  (via drill 0.61)
  Top 0.254: v99.69,40.64 99.69,22.23 100.97,20.95 E19.2
  Bottom 0.254: v99.69,40.64 98.42,41.91 91.44,41.91 90.17,43.18 E8.3
MR
  Bottom 0.254: E10.4 153.67,40.64 157.48,36.83 168.91,36.83 172.09,33.66 172.09,27.3 177.16,27.3 180.97,23.5 180.97,21.59 184.15,21.59 184.78,20.95 184.78,15.88 183.51,15.88 E5.21
N$1
  Bottom 0.254: E16.9 36.83,43.18 39.37,45.72 40.01,45.72 B.13
N$2
  Top 0.254: E9.1 217.17,40.64 216.53,40.64 PAD1.1
N$3
  Top 0.254: E9.2 217.17,38.1 216.53,38.1 PAD2.1
N$4
  Top 0.254: E9.3 217.17,35.56 216.53,35.56 PAD3.1
N$5
  Bottom 0.254: E16.15 36.83,58.42 39.37,60.96 40.01,60.96 B.1
N$6
  Bottom 0.254: E16.14 36.83,55.88 39.37,58.42 40.01,58.42 B.3
N$7
  Bottom 0.254: E16.13 36.83,53.34 39.37,55.88 40.01,55.88 B.5
N$8
  Bottom 0.254: E16.12 36.83,50.8 39.37,53.34 40.01,53.34 B.7
N$9
  Bottom 0.254: E16.11 36.83,48.26 39.37,50.8 40.01,50.8 B.9
N$10
  Bottom 0.254: E16.10 36.83,45.72 39.37,48.26 40.01,48.26 B.11
N$11
  Bottom 0.254: E16.7 29.21,45.72 33.02,41.91 38.73,41.91 40.01,43.18 B.15
N$12
  Top 0.254: E9.4 217.17,33.02 216.53,33.02 PAD4.1
N$13
  Top 0.254: X2.2 170.81,83.82 168.28,86.36 R1.2 167.64,87 167.64,88.27 C29.1
  Bottom 0.254: E3.11 184.15,78.74 180.34,82.55 173.35,82.55 172.09,83.82 X2.2
N$14
  Top 0.254: X2.1 170.81,78.74 168.28,76.2 R1.1 167.64,75.56 167.64,74.3 C28.1
  Bottom 0.254: E3.10 184.15,76.2 182.88,77.47 173.35,77.47 172.09,78.74 X2.1
N$15
  Bottom 0.508: C26.2 145.41,60.96 146.69,59.69 161.29,59.69 161.93,60.33 161.93,62.23 158.75,62.23 157.48,63.5 153.67,63.5 E12.6
N$16
  Bottom 0.508: C27.1 145.41,73.66 151.13,73.66 E12.2
N$17
  Top 0.254: R5.2 119.38,76.83 119.38,80.64 Q1.2
N$18
  Top 0.254: Q1.3 116.2,83.82 109.86,83.82 D1.A
  Bottom 0.254: R3.2 107.31,83.82 108.58,83.82 D1.A
N$19
  Top 0.254: R7.2 134.62,61.59 132.08,64.14 132.08,67.94 Q2.2
N$20
  Bottom 0.254: R8.2 120.02,71.12 121.28,71.12 D3.A 122.56,71.12 128.91,71.12 Q2.3
N$21
  Top 0.254: E9.5 217.17,30.48 216.53,30.48 PAD5.1
N$22
  Top 0.254: C24.2 147.32,62.87 150.5,59.69 150.5,57.78 151.13,57.15 154.31,57.15 154.31,64.14 153.03,65.41 E12.5
N$23
  Top 0.254: X1.1 212.72,78.74 215.26,76.2 R2.1 215.9,75.56 215.9,74.3 C30.1
  Bottom 0.254: E2.10 207.01,76.2 209.55,78.74 211.46,78.74 X1.1
N$24
  Top 0.254: R14.1 127,79.38 127,80.64 D6.C | D5.A 137.16,84.45 137.16,85.72 R13.2
  Bottom 0.254: D6.C 128.27,81.28 130.81,83.82 135.89,83.82 D5.A
N$25
  Top 0.254: X1.2 212.72,83.82 215.26,86.36 R2.2 215.9,87 215.9,88.27 C31.1
  Bottom 0.254: E2.11 206.38,79.38 210.82,83.82 211.46,83.82 X1.2
N$26
  Top 0.254: E8.11 97.16,41.27 98.42,42.55 98.42,69.22 97.16,70.48 E11.13
N$27
  Bottom 0.254: E6.12 138.43,43.18 147.32,34.29 157.48,34.29 158.75,33.02 E10.8
N$29  (via drill 0.61)
  Top 0.254: v138.43,63.5 150.5,51.44 150.5,45.09 151.13,44.45 150.5,43.81 150.5,37.47 151.76,36.2 E10.6
  Bottom 0.254: v138.43,63.5 100.33,63.5 97.79,66.04 E11.11
N$30
  Top 0.508: E10.10 159.38,38.73 158.12,40.01 158.12,43.81 159.38,45.09 E10.13
N$31
  Top 0.254: E9.6 217.17,27.94 216.53,27.94 PAD6.1
N$32
  Bottom 0.254: C25.2 147.96,71.12 151.13,71.12 E12.3
N$33
  Top 0.254: E9.7 217.17,25.4 216.53,25.4 PAD7.1
N$34
  Top 0.254: E22.1 217.17,66.04 216.53,66.04 PAD18.1
N$35
  Top 0.254: E9.8 217.17,22.86 216.53,22.86 PAD8.1
N$37
  Top 0.254: E9.16 227.33,40.64 227.97,40.64 PAD9.1
N$38
  Top 0.254: E9.15 227.33,38.1 227.97,38.1 PAD42.1
N$39
  Top 0.254: E9.14 227.33,35.56 227.97,35.56 PAD43.1
N$40
  Top 0.254: E9.13 227.33,33.02 227.97,33.02 PAD44.1
N$41
  Top 0.254: E22.2 217.17,63.5 216.53,63.5 PAD19.1
N$42
  Top 0.254: E9.12 227.33,30.48 227.97,30.48 PAD45.1
N$43
  Top 0.254: E22.3 217.17,60.96 216.53,60.96 PAD28.1
N$44
  Bottom 0.254: C24.1 147.96,68.58 151.13,68.58 E12.4
N$45
  Top 0.254: C25.1 147.96,76.2 151.13,76.2 E12.1
N$46
  Top 0.254: E9.11 227.33,27.94 227.97,27.94 PAD46.1
N$47
  Top 0.254: E9.10 227.33,25.4 227.97,25.4 PAD47.1
N$48
  Top 0.254: E9.9 227.33,22.86 227.97,22.86 PAD48.1
N$49
  Bottom 0.254: E14.15 36.83,30.48 39.37,33.02 40.01,33.02 T.1
N$50
  Top 0.254: E22.4 217.17,58.42 216.53,58.42 PAD29.1
N$51
  Top 0.254: E22.5 217.17,55.88 216.53,55.88 PAD30.1
N$52
  Top 0.254: E22.6 217.17,53.34 216.53,53.34 PAD31.1
N$53
  Top 0.254: E22.7 217.17,50.8 216.53,50.8 PAD32.1
N$54
  Top 0.254: E22.8 217.17,48.26 216.53,48.26 PAD33.1
N$55
  Top 0.254: E22.16 227.33,66.04 227.97,66.04 PAD34.1
N$56
  Top 0.254: E22.15 227.33,63.5 227.97,63.5 PAD35.1
N$57
  Top 0.254: E22.14 227.33,60.96 227.97,60.96 PAD36.1
N$58
  Top 0.254: E22.13 227.33,58.42 227.97,58.42 PAD37.1
N$59
  Top 0.254: E22.12 227.33,55.88 227.97,55.88 PAD38.1
N$60  (via drill 0.61)
  Top 0.508: E6.8 136.53,33.66 136.53,34.92 E6.9 | v154.94,33.02 v154.94,43.18
  Bottom 0.508: v154.94,43.18 158.75,43.18 E10.12 | v154.94,33.02 153.67,31.75 140.34,31.75 139.06,33.02 138.43,33.02 E6.8
N$61
  Top 0.254: E22.11 227.33,53.34 227.97,53.34 PAD39.1
N$68
  Top 0.254: E22.10 227.33,50.8 227.97,50.8 PAD40.1
N$69
  Top 0.254: E22.9 227.33,48.26 227.97,48.26 PAD41.1
N$90
  Bottom 0.254: E15.15 62.23,58.42 64.77,60.96 65.41,60.96 K.1
N$91
  Bottom 0.254: E15.14 62.23,55.88 64.77,58.42 65.41,58.42 K.3
N$97
  Bottom 0.254: E15.13 62.23,53.34 64.77,55.88 65.41,55.88 K.5
N$109
  Bottom 0.254: E15.12 62.23,50.8 64.77,53.34 65.41,53.34 K.7
N$112
  Bottom 0.254: E15.11 62.23,48.26 64.77,50.8 65.41,50.8 K.9
N$113
  Bottom 0.254: E15.10 62.23,45.72 64.77,48.26 65.41,48.26 K.11
N$114
  Bottom 0.254: E15.7 54.61,45.72 58.42,41.91 64.14,41.91 65.41,43.18 K.15
N$115
  Bottom 0.254: E15.9 62.23,43.18 64.77,45.72 65.41,45.72 K.13
N$116
  Bottom 0.254: E14.14 36.83,27.94 39.37,30.48 40.01,30.48 T.3
N$117
  Bottom 0.254: E14.13 36.83,25.4 39.37,27.94 40.01,27.94 T.5
N$118
  Bottom 0.254: E14.12 36.83,22.86 39.37,25.4 40.01,25.4 T.7
N$119
  Bottom 0.254: E14.11 36.83,20.32 39.37,22.86 40.01,22.86 T.9
N$120
  Bottom 0.254: E14.10 36.83,17.78 39.37,20.32 40.01,20.32 T.11
N$121
  Bottom 0.254: E14.7 29.21,17.78 33.02,13.97 38.73,13.97 40.01,15.24 T.15
N$122
  Bottom 0.254: E14.9 36.83,15.24 39.37,17.78 40.01,17.78 T.13
N$123
  Bottom 0.254: E13.15 62.23,30.48 64.77,33.02 65.41,33.02 P.1
N$124
  Bottom 0.254: E13.14 62.23,27.94 64.77,30.48 65.41,30.48 P.3
N$125
  Bottom 0.254: E13.13 62.23,25.4 64.77,27.94 65.41,27.94 P.5
N$126
  Bottom 0.254: E13.12 62.23,22.86 64.77,25.4 65.41,25.4 P.7
N$127
  Bottom 0.254: E13.11 62.23,20.32 64.77,22.86 65.41,22.86 P.9
N$128
  Bottom 0.254: E13.10 62.23,17.78 64.77,20.32 65.41,20.32 P.11
N$129
  Bottom 0.254: E13.7 54.61,17.78 58.42,13.97 64.14,13.97 65.41,15.24 P.15
N$130
  Bottom 0.254: E13.9 62.23,15.24 64.77,17.78 65.41,17.78 P.13
P\  (via drill 0.61)
  Top 0.254: P.16 68.58,15.88 68.58,17.14 P.14 68.58,18.41 68.58,19.68 P.12 68.58,20.95 68.58,22.23 P.10 68.58,23.5 68.58,24.77 P.8 68.58,26.04 68.58,27.3 P.6 68.58,28.57 68.58,29.84 P.4 68.58,31.11 68.58,32.38 P.2 | v120.65,30.48 v125.73,35.56
  Bottom 0.254: v125.73,35.56 128.27,38.1 E6.5 | v120.65,30.48 69.22,30.48 P.4
PT
  Bottom 0.254: E8.9 97.79,35.56 99.06,36.83 114.3,36.83 115.57,35.56 E7.9 117.47,36.2 123.19,41.91 | 123.19,41.91 127,41.91 128.27,40.64 E6.4 | 123.19,41.91 111.76,41.91 110.49,40.64 E7.4
RBR1  (via drill 0.61)
  Top 0.254: v158.75,28.57 v161.29,31.11
  Bottom 0.254: v158.75,28.57 88.9,28.57 88.9,23.5 E20.1 | v161.29,31.11 165.74,35.56 166.37,35.56 E5.12
RBR2  (via drill 0.61)
  Top 0.254: v92.71,25.4 92.71,13.97 87.63,13.97 84.45,17.14 E21.6 | v163.83,27.3 165.74,29.21 165.74,36.2 167,37.47 E5.11
  Bottom 0.254: v92.71,25.4 94.61,27.3 v163.83,27.3
RBR3  (via drill 0.61)
  Top 0.254: v163.83,8.89 169.54,14.61 169.54,38.73 168.28,40.01 E5.10
  Bottom 0.254: v163.83,8.89 156.84,8.89 155.57,7.62 99.06,7.62 97.79,8.89 74.3,8.89 74.3,20.95 75.56,22.23 E21.1
RBR4  (via drill 0.61)
  Top 0.254: v149.86,44.45 149.86,25.4 151.76,23.5 E4.1
  Bottom 0.254: v149.86,44.45 165.1,44.45 166.37,43.18 E5.9
RBR5
  Top 0.254: E17.6 148.59,17.78 150.5,17.78 150.5,18.41 151.13,19.05 158.12,19.05 158.12,13.34 163.83,7.62 170.18,7.62 170.18,43.18 168.28,45.09 E5.8
RBR6  (via drill 0.61)
  Top 0.254: v146.05,49.53 139.7,43.18 139.7,23.5 E17.1
  Bottom 0.254: v146.05,49.53 165.1,49.53 166.37,48.26 E5.7
RBR7  (via drill 0.61)
  Top 0.254: v127.64,49.53 127,48.9 127,23.5 E18.1
  Bottom 0.254: v127.64,49.53 144.78,49.53 146.69,51.44 152.4,51.44 153.03,52.07 165.1,52.07 166.37,50.8 E5.6
RBR8  (via drill 0.61)
  Top 0.254: v112.39,50.16 112.39,20.95 109.86,18.41 E19.6
  Bottom 0.254: v112.39,50.16 114.3,52.07 151.76,52.07 153.03,53.34 166.37,53.34 E5.5
RRUN
  Bottom 0.254: 123.83,62.23 124.46,61.59 R7.1 | 123.83,62.23 123.19,62.87 102.23,62.87 97.79,58.42 E11.8 | 123.83,62.23 157.48,62.23 158.75,60.96 E12.10
RRUN+
  Top 0.254: R10.2 127,56.52 127,57.78 D4.C | X3.6 114.3,99.69 120.65,93.34 120.65,63.5 121.92,62.23 D3.C
  Bottom 0.254: D3.C 122.56,60.33 124.46,58.42 125.73,58.42 D4.C
RRUN-
  Bottom 0.254: R9.2 116.84,71.75 105.41,83.19 105.41,99.69 104.14,99.69 X3.4
RTS
  Top 0.254: E12.8 151.76,59.05 151.76,60.33 E12.7 151.76,61.59 150.5,62.87 150.5,69.85 140.97,79.38 140.97,97.16 J1.8
RX  (via drill 0.61)
  Top 0.254: v147.32,41.91 v143.51,45.72 | v157.48,35.56 157.48,28.57 161.93,24.13 161.93,20.95 167,15.88 E5.20
  Bottom 0.254: v143.51,45.72 138.43,45.72 E6.13 | v147.32,41.91 151.13,38.1 E10.5 153.67,38.1 154.94,38.1 v157.48,35.56
RX+
  Bottom 0.254: 130.18,88.9 127.64,86.36 R13.1 | 130.18,88.9 136.53,88.9 R11.1 | 130.18,88.9 119.38,99.69 X3.7
RX-
  Top 0.254: R12.2 104.14,84.45 99.06,89.53 99.06,99.69 X3.3
RXD
  Top 0.254: E12.13 160.66,69.22 161.93,70.48 161.93,91.44 153.67,99.69 139.7,99.69 139.7,95.89 J1.3
RXE
  Top 0.254: E10.9 160.66,36.2 161.93,37.47 161.93,64.14 160.66,65.41 E12.12
RXL\
  Top 0.254: E6.11 137.79,41.27 139.06,42.55 139.06,61.59 137.16,63.5 137.16,78.11 R14.2
STOPB
  Top 0.254: E5.36 184.15,53.34 188.59,53.34 188.59,51.44 189.23,50.8 STOPB.2
T\
  Top 0.254: T.16 43.18,15.88 43.18,17.14 T.14 43.18,18.41 43.18,19.68 T.12 43.18,20.95 43.18,22.23 T.10 43.18,23.5 43.18,24.77 T.8 43.18,26.04 43.18,27.3 T.6 43.18,28.57 43.18,29.84 T.4 43.18,31.11 43.18,32.38 T.2
  Bottom 0.254: E6.6 128.27,35.56 127,34.29 107.95,34.29 105.41,31.75 71.75,31.75 69.22,34.29 45.09,34.29 43.81,33.02 T.2
TBR1
  Bottom 0.254: E5.26 184.15,27.94 185.42,29.21 207.01,29.21 207.65,29.84 207.65,40.01 206.38,40.01 E1.18
TBR2
  Top 0.254: E5.27 182.25,31.11 180.97,32.38 180.97,43.81 181.61,44.45 207.65,44.45 207.65,37.47 206.38,36.2 E1.16
TBR3
  Bottom 0.254: E5.28 184.15,33.02 185.42,31.75 203.2,31.75 204.47,30.48 E1.14
TBR4
  Bottom 0.254: E5.29 184.15,35.56 184.78,36.2 196.22,36.2 196.85,36.83 199.39,36.83 204.47,41.91 207.01,41.91 208.28,40.64 208.28,26.04 206.38,26.04 E1.12
TBR5
  Bottom 0.254: E5.30 182.25,37.47 180.97,36.2 180.97,26.67 195.58,26.67 196.85,25.4 E1.9
TBR6  (via drill 0.61)
  Top 0.254: v191.77,38.73 196.22,34.29 196.22,32.38 197.49,31.11 E1.7
  Bottom 0.254: v191.77,38.73 186.06,38.73 184.15,40.64 E5.31
TBR7
  Top 0.254: E5.32 184.15,43.18 196.22,43.18 196.22,37.47 197.49,36.2 E1.5
TBR8
  Bottom 0.254: E5.33 184.15,45.72 189.23,40.64 196.85,40.64 E1.3
TCF\  (via drill 0.61)
  Top 0.254: v86.36,34.29 86.36,71.12 88.27,73.03 E11.1
  Bottom 0.254: v86.36,34.29 106.68,34.29 107.95,35.56 E7.6
TPC\
  Bottom 0.254: E7.8 118.11,33.02 119.38,31.75 139.06,31.75 140.97,29.84 163.19,29.84 166.37,26.67 176.53,26.67 180.34,22.86 180.34,20.95 182.25,20.95 E5.23
TPF
  Top 0.254: 99.06,15.24 100.33,13.97 107.31,13.97 107.31,15.88 107.95,16.51 112.39,16.51 112.39,18.41 113.67,19.68 E23.2 113.67,20.95 113.67,22.23 E23.1 | 99.06,15.24 97.16,17.14 E20.6 | 99.06,15.24 99.06,39.37 95.25,39.37 94.61,40.01 94.61,49.53 89.53,49.53 87,52.07 87,61.59 88.27,62.87 E11.5
TRE  (via drill 0.61)
  Top 0.254: v173.99,67.31 177.8,63.5 177.8,22.86 179.07,21.59 181.61,21.59 181.61,22.86 E5.24
  Bottom 0.254: v173.99,67.31 91.44,67.31 90.17,68.58 E11.3
TSF
  Top 0.254: E20.7 97.16,20.95 98.42,22.23 98.42,31.11 97.16,32.38 E8.8
TX  (via drill 0.61)
  Top 0.254: v135.89,66.04 135.89,69.22 129.54,75.56 R5.1 | v180.34,50.8 180.34,27.94 182.25,26.04 E5.25
  Bottom 0.254: v135.89,66.04 137.16,64.77 157.48,64.77 158.75,63.5 E12.11 161.29,63.5 161.93,63.5 163.19,62.23 168.91,62.23 v180.34,50.8
TX+
  Top 0.254: R6.2 114.3,69.22 114.3,70.48 D2.C | X3.5 109.22,99.69 107.95,98.42 107.95,76.2 109.22,74.93 D1.C
  Bottom 0.254: D1.C 109.86,73.03 111.76,71.12 113.03,71.12 D2.C
TX-
  Top 0.254: R4.2 101.6,84.45 94.61,91.44 94.61,99.69 X3.2
TXD
  Bottom 0.254: E12.14 161.29,71.12 162.56,72.39 173.35,72.39 173.99,73.03 173.99,76.83 168.91,76.83 152.4,93.34 138.43,93.34 137.16,94.61 J1.2
VCC
  Top 0.508: E14.16 34.92,33.66 34.92,34.29 34.29,34.92 C10.1 34.29,36.2 33.66,36.83 33.66,63.5 C12.1 34.29,62.87 34.92,62.23 34.92,61.59 E16.16 | C13.1 95.25,75.56 95.89,74.93 95.89,74.3 E11.14 | E8.14 95.89,48.9 95.25,49.53 95.25,50.16 C3.1 95.25,51.44 94.61,52.07 94.61,61.59 | 94.61,61.59 95.89,62.87 E11.10 | 94.61,61.59 94.61,66.67 95.89,67.94 E11.12 | E13.16 60.33,33.66 60.33,34.29 59.69,34.92 C9.1 59.69,36.2 59.05,36.83 59.05,40.01 | C22.1 68.58,90.81 75.56,97.79 C23.+ 77.47,99.69 85.72,107.95 85.72,108.58 111.12,108.58 116.2,103.5 116.2,100.33 127,89.53 R11.2 127,88.27 125.73,87 125.73,83.82 D5.C 126.36,83.19 125.09,81.92 125.09,71.12 129.54,66.67 Q2.1 129.54,65.41 133.35,61.59 133.35,53.98 135.89,51.44 C1.1 135.89,50.16 135.89,49.53 136.53,48.9 E6.14 136.53,47.62 133.35,44.45 133.35,26.04 C17.1 133.35,24.77 133.35,24.13 133.99,23.5 E18.8 | E15.16 60.33,61.59 60.33,62.23 59.69,62.87 C11.1 59.05,63.5 59.05,40.01 | C20.1 95.25,24.77 95.89,24.13 95.89,23.5 E20.8 | E4.8 159.38,23.5 158.75,24.13 158.75,24.77 C7.1 | E17.8 146.69,23.5 146.05,24.13 146.05,24.77 C16.1 | C2.1 115.57,50.16 115.57,49.53 116.2,48.9 E7.14 117.47,47.62 119.38,45.72 119.38,27.3 120.65,26.04 C18.1 120.65,24.77 120.65,24.13 121.28,23.5 E23.8 | E19.8 108.58,23.5 107.95,24.13 107.95,24.77 C19.1 | C6.1 184.15,93.34 184.78,92.71 184.78,92.08 E3.16 184.78,90.81 179.71,85.72 179.71,68.58 177.8,66.67 C8.1 | C5.1 204.47,93.34 205.1,92.71 205.1,92.08 E2.16 | E1.20 205.1,46.35 204.47,46.99 204.47,47.62 C4.1 | E5.34 182.25,48.9 182.25,50.16 E5.35 | E5.39 183.51,60.33 189.87,53.98 STOPB.3
  Top 0.508: E10.14 159.38,48.9 159.38,49.53 158.75,50.16 C15.1 158.75,51.44 158.12,52.07 158.12,67.31 | E12.16 159.38,76.83 158.75,77.47 158.75,78.11 C14.1 158.12,78.74 158.12,67.31 | 158.12,67.31 162.56,67.31 166.37,63.5 E5.1 | 59.05,40.01 83.19,40.01 83.19,23.5 E21.8
  Bottom 0.508: E14.6 28.57,20.95 33.66,26.04 33.66,33.02 34.29,33.02 E14.16 | E16.6 28.57,48.9 33.66,53.98 33.66,60.96 34.29,60.96 E16.16 36.83,60.96 40.64,64.77 41.91,64.77 | 91.44,72.39 92.71,73.66 95.25,73.66 E11.14 | 91.44,72.39 90.17,71.12 E11.2 | 91.44,72.39 95.25,68.58 E11.12 | E11.10 95.25,63.5 92.71,63.5 90.17,66.04 E11.4 87.63,66.04 85.09,63.5 60.33,63.5 C11.1 59.05,63.5 57.78,64.77 41.91,64.77 | E13.6 53.98,20.95 59.05,26.04 59.05,33.02 59.69,33.02 E13.16 | E15.6 53.98,48.9 59.05,53.98 59.05,60.96 59.69,60.96 E15.16 | E21.8 85.09,22.86 86.36,21.59 93.98,21.59 95.25,22.86 E20.8 97.79,22.86 99.06,24.13 111.76,24.13 | 111.76,24.13 110.49,22.86 E19.8 | 118.75,24.13 111.76,24.13 | 118.75,24.13 120.02,25.4 C18.1 | 131.44,24.13 132.72,25.4 C17.1 | 131.44,24.13 118.75,24.13 | 131.44,24.13 144.15,24.13 145.41,25.4 C16.1 | C7.1 158.12,25.4 156.84,26.67 152.4,26.67 148.59,22.86 E17.8 | C21.1 224.79,69.22 224.79,90.81 206.38,90.81 E2.16 | C6.1 184.78,93.98 186.06,95.25 202.56,95.25 203.84,93.98 C5.1 | 177.8,60.96 181.61,60.96 E5.39 184.15,60.96 186.69,60.96 189.23,63.5 5/8.3 | 177.8,60.96 171.45,60.96 168.91,63.5 E5.1 | 177.8,60.96 177.8,65.41 C8.1 | E5.35 184.15,50.8 186.69,50.8 189.23,53.34 STOPB.3 191.77,53.34 198.75,53.34 203.84,48.26 C4.1 | 124.46,82.55 116.84,82.55 116.84,79.38 Q1.1 | 124.46,82.55 125.73,83.82 D5.C | 146.69,80.01 145.41,78.74 C27.2 | 146.69,80.01 156.84,80.01 158.12,78.74 C14.1 | 124.46,82.55 124.46,80.01 146.69,80.01 | 41.91,64.77 41.91,75.56 IC2.3

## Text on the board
Bottom: Posibus Serial Interface | VRS
tPlace: Posibus Serial Interface | VRS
